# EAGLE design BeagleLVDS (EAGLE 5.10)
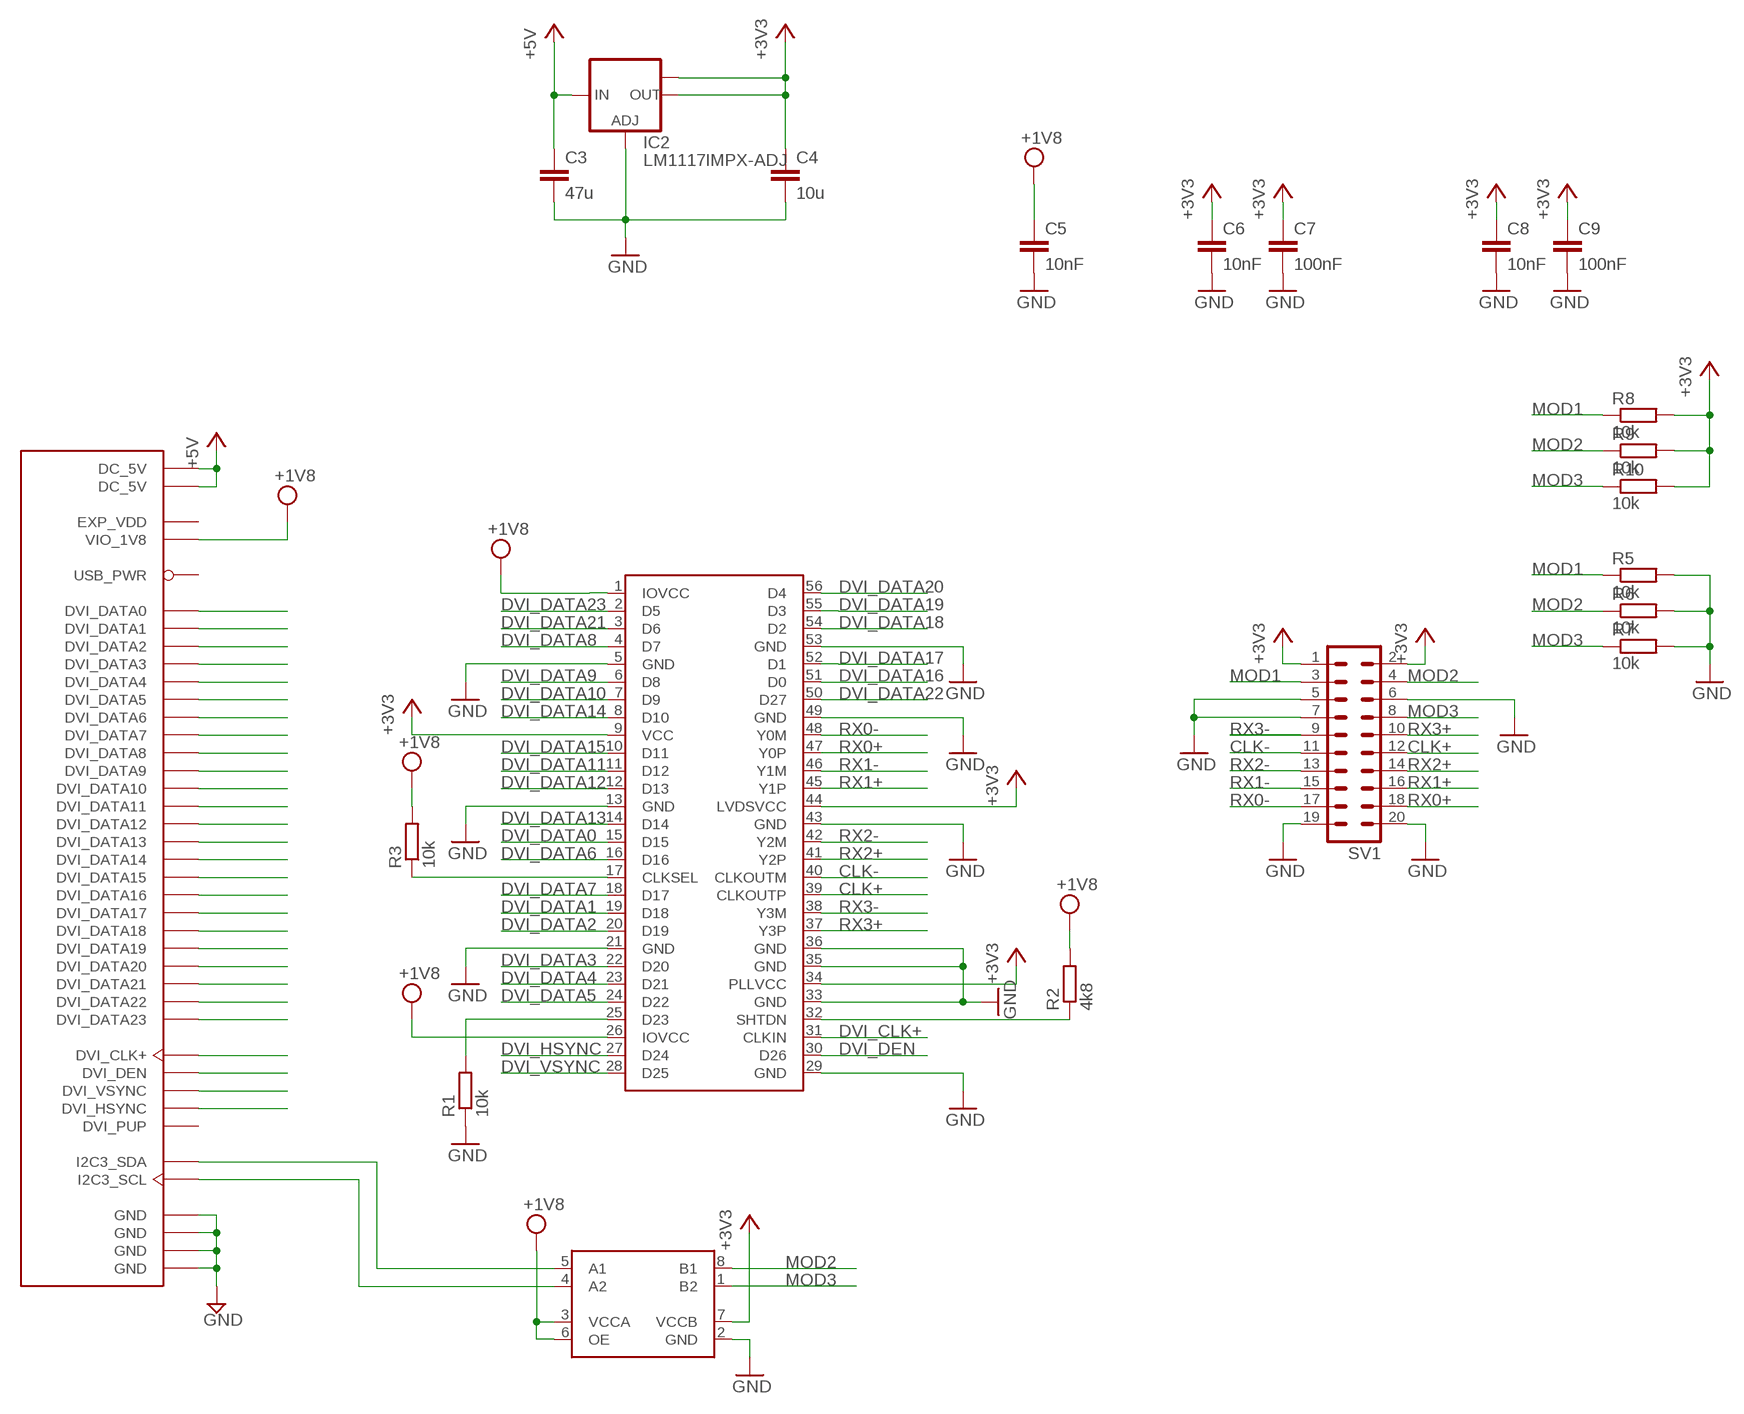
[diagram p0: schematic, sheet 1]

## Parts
C3  47u  C-EUC1206  [C1206]
C4  10u  C-EUC1206  [C1206]
C5  10nF  C-EUC0402  [C0402]
C6  10nF  C-EUC0402  [C0402]
C7  100nF  C-EUC0603  [C0603]
C8  10nF  C-EUC0402  [C0402]
C9  100nF  C-EUC0603  [C0603]
DCU1  TXS0102  [DCU]
IC2  LM1117IMPX-ADJ  [SOT223]
R1  10k  R-EU_R0402  [R0402]
R2  4k8  R-EU_R0402  [R0402]
R3  10k  R-EU_R0402  [R0402]
R5  10k  R-EU_R0402  [R0402]
R6  10k  R-EU_R0402  [R0402]
R7  10k  R-EU_R0402  [R0402]
R8  10k  R-EU_R0402  [R0402]
R9  10k  R-EU_R0402  [R0402]
R10  10k  R-EU_R0402  [R0402]
SV1  MA10-2  [MA10-2]
U$1  LCD_EXPANSION_HEADERSSMALL_PADS  LCD_EXPANSION_HEADERS  [MALE_HEADER_2X10_50MIL]
U$2  SN75LVDS83B  [PSOP56]

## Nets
+1V8: C5.1 DCU1.3(VCCA) DCU1.6(OE) R2.2 R3.2 U$1.P13_2(VIO_1V8) U$2.1(IOVCC) U$2.26(IOVCC)
+3V3: C4.1 C6.1 C7.1 C8.1 C9.1 DCU1.7(VCCB) IC2.2(OUT) IC2.TAB(OUT1) R8.2 R9.2 R10.2 SV1.1 SV1.2 U$2.9(VCC) U$2.34(PLLVCC) U$2.44(LVDSVCC)
+5V: C3.1 IC2.3(IN) U$1.P11_1(DC_5V) U$1.P11_2(DC_5V)
CLK+: SV1.12 U$2.39(CLKOUTP)
CLK-: SV1.11 U$2.40(CLKOUTM)
DVI_CLK+: U$1.P13_16(DVI_CLK+) U$2.31(CLKIN)
DVI_DATA0: U$1.P11_4(DVI_DATA0) U$2.15(D15)
DVI_DATA1: U$1.P11_3(DVI_DATA1) U$2.19(D18)
DVI_DATA2: U$1.P11_6(DVI_DATA2) U$2.20(D19)
DVI_DATA3: U$1.P11_5(DVI_DATA3) U$2.22(D20)
DVI_DATA4: U$1.P11_8(DVI_DATA4) U$2.23(D21)
DVI_DATA5: U$1.P11_7(DVI_DATA5) U$2.24(D22)
DVI_DATA6: U$1.P13_15(DVI_DATA6) U$2.16(D16)
DVI_DATA7: U$1.P13_9(DVI_DATA7) U$2.18(D17)
DVI_DATA8: U$1.P13_11(DVI_DATA8) U$2.4(D7)
DVI_DATA9: U$1.P13_13(DVI_DATA9) U$2.6(D8)
DVI_DATA10: U$1.P11_10(DVI_DATA10) U$2.7(D9)
DVI_DATA11: U$1.P11_16(DVI_DATA11) U$2.11(D12)
DVI_DATA12: U$1.P11_9(DVI_DATA12) U$2.12(D13)
DVI_DATA13: U$1.P13_10(DVI_DATA13) U$2.14(D14)
DVI_DATA14: U$1.P11_12(DVI_DATA14) U$2.8(D10)
DVI_DATA15: U$1.P13_7(DVI_DATA15) U$2.10(D11)
DVI_DATA16: U$1.P13_8(DVI_DATA16) U$2.51(D0)
DVI_DATA17: U$1.P13_5(DVI_DATA17) U$2.52(D1)
DVI_DATA18: U$1.P13_6(DVI_DATA18) U$2.54(D2)
DVI_DATA19: U$1.P11_13(DVI_DATA19) U$2.55(D3)
DVI_DATA20: U$1.P13_3(DVI_DATA20) U$2.56(D4)
DVI_DATA21: U$1.P13_4(DVI_DATA21) U$2.3(D6)
DVI_DATA22: U$1.P11_14(DVI_DATA22) U$2.50(D27)
DVI_DATA23: U$1.P11_11(DVI_DATA23) U$2.2(D5)
DVI_DEN: U$1.P13_17(DVI_DEN) U$2.30(D26)
DVI_HSYNC: U$1.P13_18(DVI_HSYNC) U$2.27(D24)
DVI_VSYNC: U$1.P11_17(DVI_VSYNC) U$2.28(D25)
GND: C3.2 C4.2 C5.2 C6.2 C7.2 C8.2 C9.2 DCU1.2(GND) IC2.1(ADJ) R1.1 R5.2 R6.2 R7.2 SV1.5 SV1.6 SV1.7 SV1.19 SV1.20 U$1.P11_19(GND) U$1.P11_20(GND) U$1.P13_19(GND) U$1.P13_20(GND) U$2.5(GND) U$2.13(GND) U$2.21(GND) U$2.29(GND) U$2.33(GND) U$2.35(GND) U$2.36(GND) U$2.43(GND) U$2.49(GND) U$2.53(GND)
MOD1: R5.1 R8.1 SV1.3
MOD2: DCU1.8(B1) R6.1 R9.1 SV1.4
MOD3: DCU1.1(B2) R7.1 R10.1 SV1.8
N$1: R3.1 U$2.17(CLKSEL)
N$2: R1.2 U$2.25(D23)
N$3: R2.1 U$2.32(SHTDN)
N$5: DCU1.5(A1) U$1.P11_15(I2C3_SDA)
N$6: DCU1.4(A2) U$1.P13_14(I2C3_SCL)
RX0+: SV1.18 U$2.47(Y0P)
RX0-: SV1.17 U$2.48(Y0M)
RX1+: SV1.16 U$2.45(Y1P)
RX1-: SV1.15 U$2.46(Y1M)
RX2+: SV1.14 U$2.41(Y2P)
RX2-: SV1.13 U$2.42(Y2M)
RX3+: SV1.10 U$2.37(Y3P)
RX3-: SV1.9 U$2.38(Y3M)
Unconnected: U$1.P11_18(DVI_PUP) U$1.P13_1(EXP_VDD) U$1.P13_12(USB_PWR)

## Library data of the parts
C3-C9 = rcl:C-EU: CAPACITOR, European symbol
DCU1 = TXS0102:TXS0102
IC2 = lm1117:LM1117IMPX-ADJ
R1-R3 R5-R10 = rcl:R-EU_: RESISTOR, European symbol
SV1 = con-lstb:MA10-2: PIN HEADER
U$1 = Beagleboard-XM:LCD_EXPANSION_HEADERS
U$2 = SN75LVDS83B:SN75LVDS83B

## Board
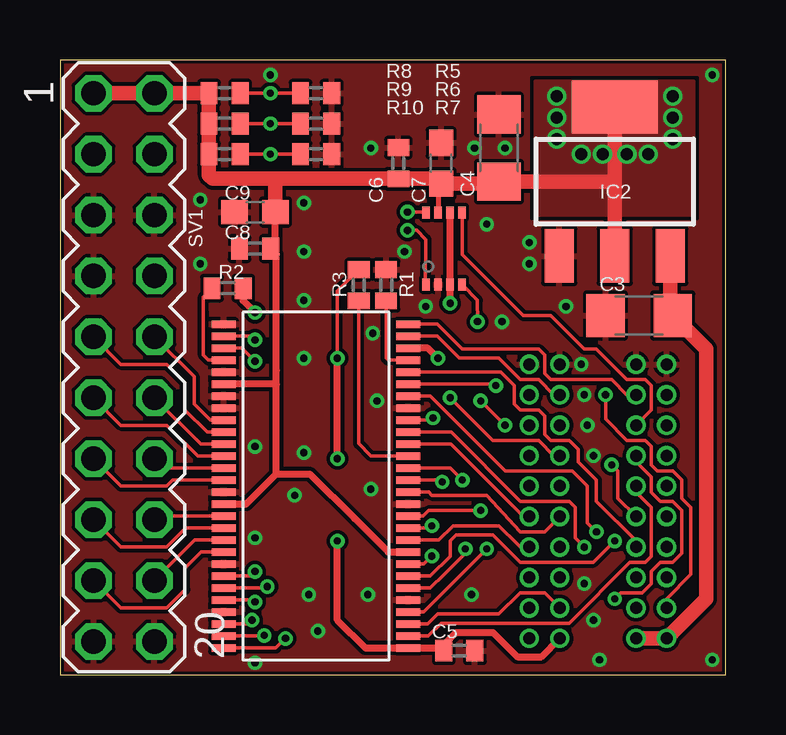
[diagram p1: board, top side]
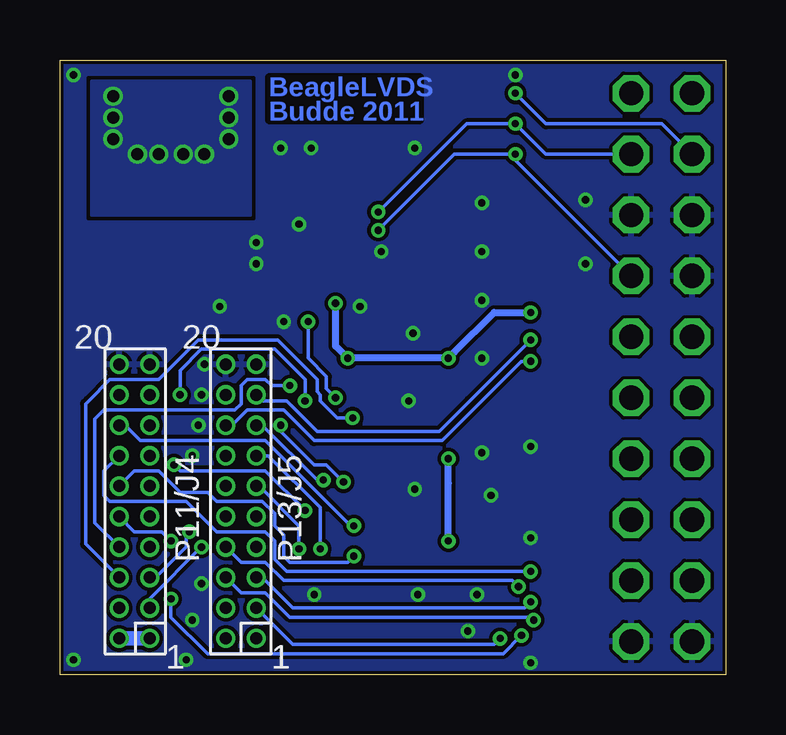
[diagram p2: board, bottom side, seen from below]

Size 27.74 x 25.64 mm. Coordinates in mm from the lower left corner, seen from the top.
Outline: 0,0 27.74,0 27.74,25.64 0,25.64 0,0
Copper layers (1*16): Top 0.035mm / dielectric 1.5mm / Bottom 0.035mm
Design rules "2layer_20110407": minimum track width 0.15mm, minimum drill 0.3mm, track to track 0.15mm, track to pad 0.15mm, pad to pad 0.15mm, via to via 0.15mm, smd to smd 0.15mm, copper to edge 0.15mm, drill to drill 0.2mm, minimum pad ring 0.15mm, minimum via ring 0.15mm, stop-mask expansion 0.15mm, vias tented up to drill 0.3mm, thermal gap 0.15mm

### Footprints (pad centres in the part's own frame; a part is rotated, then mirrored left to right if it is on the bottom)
C1206 = smd 1.6 x 1.8: 1 -1.4,0; 2 1.4,0
C0402 = smd 0.7 x 0.9: 1 -0.65,0; 2 0.65,0
C0603 = smd 1.1 x 1: 1 -0.85,0; 2 0.85,0
DCU = smd 0.3 x 0.5: 1 -0.75,-1.5; 2 -0.25,-1.5; 3 0.25,-1.5; 4 0.75,-1.5; 5 0.75,1.5; 6 0.25,1.5; 7 -0.25,1.5; 8 -0.75,1.5
SOT223 = smd 1.219 x 2.235: 1 -2.311,-3.099; 2 0,-3.099; 3 2.311,-3.099 | smd 3.6 x 2.2: TAB 0,3.099
R0402 = smd 0.7 x 0.9: 1 -0.65,0; 2 0.65,0
MA10-2 = drill 1.016 octagon: 1 -11.43,-1.27; 2 -11.43,1.27; 3 -8.89,-1.27; 4 -8.89,1.27; 5 -6.35,-1.27; 6 -6.35,1.27; 7 -3.81,-1.27; 8 -3.81,1.27; 9 -1.27,-1.27; 10 -1.27,1.27; 11 1.27,-1.27; 12 1.27,1.27; 13 3.81,-1.27; 14 3.81,1.27; 15 6.35,-1.27; 16 6.35,1.27; 17 8.89,-1.27; 18 8.89,1.27; 19 11.43,-1.27; 20 11.43,1.27
MALE_HEADER_2X10_50MIL = drill 0.5 pad 0.8 round: P11_1 -1.778,-5.715; P11_2 -3.048,-5.715; P11_3 -1.778,-4.445; P11_4 -3.048,-4.445; P11_5 -1.778,-3.175; P11_6 -3.048,-3.175; P11_7 -1.778,-1.905; P11_8 -3.048,-1.905; P11_9 -1.778,-0.635; P11_10 -3.048,-0.635; P11_11 -1.778,0.635; P11_12 -3.048,0.635; P11_13 -1.778,1.905; P11_14 -3.048,1.905; P11_15 -1.778,3.175; P11_16 -3.048,3.175; P11_17 -1.778,4.445; P11_18 -3.048,4.445; P11_19 -1.778,5.715; P11_20 -3.048,5.715; P13_1 2.667,-5.715; P13_2 1.397,-5.715; P13_3 2.667,-4.445; P13_4 1.397,-4.445; P13_5 2.667,-3.175; P13_6 1.397,-3.175; P13_7 2.667,-1.905; P13_8 1.397,-1.905; P13_9 2.667,-0.635; P13_10 1.397,-0.635; P13_11 2.667,0.635; P13_12 1.397,0.635; P13_13 2.667,1.905; P13_14 1.397,1.905; P13_15 2.667,3.175; P13_16 1.397,3.175; P13_17 2.667,4.445; P13_18 1.397,4.445; P13_19 2.667,5.715; P13_20 1.397,5.715
PSOP56 = smd 0.3 x 1: 1 -6.75,-3.85; 2 -6.25,-3.85; 3 -5.75,-3.85; 4 -5.25,-3.85; 5 -4.75,-3.85; 6 -4.25,-3.85; 7 -3.75,-3.85; 8 -3.25,-3.85; 9 -2.75,-3.85; 10 -2.25,-3.85; 11 -1.75,-3.85; 12 -1.25,-3.85; 13 -0.75,-3.85; 14 -0.25,-3.85; 15 0.25,-3.85; 16 0.75,-3.85; 17 1.25,-3.85; 18 1.75,-3.85; 19 2.25,-3.85; 20 2.75,-3.85; 21 3.25,-3.85; 22 3.75,-3.85; 23 4.25,-3.85; 24 4.75,-3.85; 25 5.25,-3.85; 26 5.75,-3.85; 27 6.25,-3.85; 28 6.75,-3.85; 29 6.75,3.85; 30 6.25,3.85; 31 5.75,3.85; 32 5.25,3.85; 33 4.75,3.85; 34 4.25,3.85; 35 3.75,3.85; 36 3.25,3.85; 37 2.75,3.85; 38 2.25,3.85; 39 1.75,3.85; 40 1.25,3.85; 41 0.75,3.85; 42 0.25,3.85; 43 -0.25,3.85; 44 -0.75,3.85; 45 -1.25,3.85; 46 -1.75,3.85; 47 -2.25,3.85; 48 -2.75,3.85; 49 -3.25,3.85; 50 -3.75,3.85; 51 -4.25,3.85; 52 -4.75,3.85; 53 -5.25,3.85; 54 -5.75,3.85; 55 -6.25,3.85; 56 -6.75,3.85

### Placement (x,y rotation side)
C3  24.13,14.99 180 top
C4  18.29,21.97 90 top
C5  16.64,1.02 0 top
C6  14.1,21.34 90 top
C7  15.88,21.34 90 top
C8  8.13,17.78 180 top
C9  8.13,19.3 180 top
DCU1  16,17.78 0 top
IC2  23.11,20.57 0 top
R1  13.59,16.26 270 top
R2  6.99,16.13 0 top
R3  12.45,16.26 90 top
R5  10.67,24.26 0 top
R6  10.67,22.99 0 top
R7  10.67,21.72 0 top
R8  6.86,24.26 180 top
R9  6.86,22.99 180 top
R10  6.86,21.72 180 top
SV1  2.67,12.83 270 top
U$1  22.23,7.24 0 bottom
U$2  10.67,7.87 90 top

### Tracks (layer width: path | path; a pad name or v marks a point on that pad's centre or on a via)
+1V8  (via drill 0.3 pad 0.6)
  Top 0.15: R3.2 11.56,16.02 v11.56,13.21
  Top 0.3: U$1.P13_2 20.07,0.76 19.05,0.76 18.8,1.02 18.03,1.78 16.51,1.78 16,1.28 C5.1 15.88,1.12 U$2.1 12.72,1.12 11.56,2.29 v11.56,5.59 | U$2.26 15.33,13.62 v15.75,13.21 | R2.2 7.63,15.61 v8.13,15.11 | v16.26,15.49 16.26,15.89 DCU1.3 DCU1.6 | v11.56,9.02 v11.56,13.21
  Bottom 0.3: v11.56,5.59 11.56,8 v11.56,9.02 | v8.13,15.11 9.65,15.11 11.3,13.46 v11.56,13.21 v15.75,13.21 16.26,13.72 v16.26,15.49
+3V3  (via drill 0.5 pad 0.6)
  Top 0.2: DCU1.7 15.75,20.57 C4.1
  Top 0.3: 9.02,12.12 8.95,12.12 U$2.34 9.02,12.12 | U$2.9 13.67,5.12 12.28,6.52 10.41,8.38 9.02,8.38 | R10.2 6.22,21.7 | C9.1 8.98,17.98 C8.1 9.02,17.54 9.02,12.7 9.02,12.12 | 9.02,8.38 9.02,12.12 | U$2.44 7.76,7.12 9.02,8.38
  Top 0.61: SV1.1 SV1.2 R8.2 R9.2 R10.2 | 23.11,20.57 IC2.TAB 23.11,20.57 | 23.11,20.57 IC2.2 | 23.11,20.57 C4.1 18.67,20.49 C7.1 15.88,20.69 C6.1 6.37,20.69 | 6.37,20.69 6.22,20.83 6.21,20.84 | 6.21,20.84 R10.2 | 6.21,20.84 R10.2 | 6.37,20.69 8.98,20.69 C9.1
  other vias: 20.7,24.13 20.7,23.24 22.61,21.72 24.51,21.72 25.53,24.13 25.53,23.24 25.53,22.35 21.72,21.72 23.62,21.72 20.7,22.35
  pour Top (isolate 0.254, no thermals): 19.81,24.77 19.81,19.18 26.42,19.18 26.42,24.77
  pour Bottom (isolate 0.254, no thermals): 19.81,24.77 19.81,19.18 26.42,19.18 26.42,24.77
+5V
  Top 0.61: IC2.3 25.43,15.01 C3.1 26.92,13.59 26.92,13.08 26.92,3.17 U$1.P11_2 U$1.P11_1
  Bottom 0.61: U$1.P11_2 U$1.P11_1
CLK+
  Top 0.15: U$2.39 5.87,9.62 SV1.12
CLK-
  Top 0.15: U$2.40 5.74,9.12 4.45,10.41 2.54,10.41 SV1.11
DVI_CLK+  (via drill 0.3 pad 0.6)
  Top 0.15: v8.13,13.08 7.75,13.46 7.58,13.62 U$2.31
  Bottom 0.15: U$1.P13_16 20.57,10.41 19.94,11.05 18.41,11.05 17.14,9.78 11.81,9.78 8.51,13.08 v8.13,13.08
DVI_DATA0  (via drill 0.3 pad 0.6)
  Top 0.15: U$1.P11_4 25.27,3.17 26.29,4.19 26.29,6.99 25.91,7.37 25.91,8.13 25.53,8.51 25.02,8.51 24.89,8.51 24.64,8.76 24.64,9.53 24.38,9.78 23.62,9.78 22.73,10.67 v22.73,11.68 | U$2.15 15.85,8.13 v15.93,8.05 | v18.54,10.41 v17.53,11.43
  Bottom 0.15: v17.53,11.43 17.53,12.32 18.8,13.59 19.3,13.59 21.84,13.59 22.73,12.7 v22.73,11.68 | v15.93,8.05 16.64,8.76 17.14,8.76 18.54,10.16 v18.54,10.41
DVI_DATA1  (via drill 0.3 pad 0.6)
  Top 0.15: U$2.19 16.29,10.12 19.18,7.24 21.21,7.24 21.46,6.99 21.46,5.71 v21.84,5.33
  Bottom 0.15: v21.84,5.33 24,3.17 U$1.P11_3
DVI_DATA2  (via drill 0.3 pad 0.6)
  Top 0.15: U$2.20 15.45,10.62 v15.54,10.72
  Bottom 0.15: U$1.P11_6 26.67,5.46 26.67,11.3 26.54,11.43 25.65,12.32 23.62,12.32 21.97,13.97 18.67,13.97 17.02,12.32 17.02,11.81 16.89,11.68 16.89,11.43 16.18,10.72 v15.54,10.72
DVI_DATA3  (via drill 0.3 pad 0.6)
  Top 0.15: v22.35,5.97 21.97,6.35 21.97,7.11 21.97,7.87 21.34,8.51 18.54,8.51 16.13,10.92 15.43,11.62 U$2.22
  Bottom 0.15: v22.35,5.97 22.48,5.84 22.48,5.46 22.48,5.33 23.75,4.06 U$1.P11_5
DVI_DATA4  (via drill 0.3 pad 0.6)
  Top 0.15: U$2.23 17.98,12.12 v18.16,12.06
  Bottom 0.15: v18.16,12.06 18.92,12.06 | 18.92,12.06 19.18,12.32 | 18.92,12.06 19.18,12.32 | 19.18,12.32 19.94,12.32 20.19,12.06 20.19,11.3 20.45,11.05 25.91,11.05 26.29,10.67 26.29,6.35 U$1.P11_8
DVI_DATA5
  Top 0.15: U$2.24 18.36,12.62 18.92,12.06 18.92,11.3 19.18,11.05 19.94,11.05 20.19,10.79 20.19,10.03 20.45,9.78 21.21,9.78 21.59,9.4 21.59,8.89 22.35,8.13 22.35,7.24 24,5.59 U$1.P11_7
DVI_DATA6  (via drill 0.3 pad 0.6)
  Top 0.15: v16.76,8.13 16.26,8.64 14.53,8.64 U$2.16
  Bottom 0.15: U$1.P13_15 19.3,10.41 17.02,8.13 v16.76,8.13
DVI_DATA7
  Top 0.15: U$1.P13_9 19.3,6.6 16.28,9.62 U$2.18
DVI_DATA8  (via drill 0.3 pad 0.6)
  Top 0.15: v17.78,5.26 15.15,2.62 U$2.4
  Bottom 0.15: v17.78,5.26 17.78,6.22 19.43,7.87 U$1.P13_11
DVI_DATA9  (via drill 0.3 pad 0.6)
  Top 0.15: v16.89,5.26 16.89,5.08 16,4.19 15.44,3.62 U$2.6
  Bottom 0.15: U$1.P13_13 19.05,9.14 16.89,6.99 v16.89,5.26
DVI_DATA10  (via drill 0.3 pad 0.6)
  Top 0.15: U$2.7 15.43,4.12 16.26,4.95 16.26,5.59 16.51,5.84 18.03,5.84 19.18,4.7 22.23,4.7 v23.11,5.59
  Bottom 0.15: v23.11,5.59 23.5,5.97 23.62,5.97 24.64,5.97 U$1.P11_10
DVI_DATA11  (via drill 0.3 pad 0.6)
  Top 0.15: U$2.11 15.39,6.12 v15.49,6.22
  Bottom 0.15: v15.49,6.22 15.62,6.22 19.18,9.78 24.38,9.78 25.02,10.41 U$1.P11_16
DVI_DATA12  (via drill 0.3 pad 0.6)
  Top 0.15: U$2.12 15.13,6.62 15.37,6.86 v17.53,6.86 | v22.99,8.76 23.24,8.51 23.24,7.37 U$1.P11_9
  Bottom 0.15: v17.53,6.86 19.18,8.51 22.73,8.51 v22.99,8.76
DVI_DATA13
  Top 0.15: U$1.P13_10 20.19,5.97 19.18,5.97 17.78,7.49 15.49,7.49 15.36,7.62 U$2.14
DVI_DATA14  (via drill 0.3 pad 0.6)
  Top 0.15: U$2.8 15.16,4.62 v15.49,4.95
  Bottom 0.15: v15.49,4.95 15.75,4.7 18.16,4.7 18.41,4.95 18.41,5.84 18.8,6.22 18.8,6.73 19.3,7.24 21.21,7.24 21.59,7.62 22.73,7.62 23.62,8.51 24.64,8.51 U$1.P11_12
DVI_DATA15
  Top 0.15: U$2.10 15.78,5.62 16.38,6.22 18.29,6.22 19.05,5.46 19.18,5.33 U$1.P13_7
DVI_DATA16  (via drill 0.3 pad 0.6)
  Top 0.15: U$2.51 8.58,3.62 v8.64,3.68
  Bottom 0.15: U$1.P13_8 20.19,4.7 19.18,4.7 18.41,3.94 8.89,3.94 v8.64,3.68
DVI_DATA17  (via drill 0.3 pad 0.6)
  Top 0.15: U$2.52 8.08,3.12 v8.13,3.05
  Bottom 0.15: v8.13,3.05 8.38,2.79 9.02,2.79 18.03,2.79 19.3,4.06 U$1.P13_5
DVI_DATA18  (via drill 0.3 pad 0.6)
  Top 0.15: U$2.54 7.84,2.12 v8,2.29
  Bottom 0.15: v8,2.29 8.13,2.41 18.16,2.41 19.18,3.43 20.19,3.43 U$1.P13_6
DVI_DATA19  (via drill 0.3 pad 0.6)
  Top 0.15: v23.11,3.17 23.37,3.43 24.13,3.43 24.26,3.43 24.64,3.81 24.64,4.32 25.02,4.7 25.53,4.7 25.91,5.08 25.91,6.86 25.53,7.24 25.02,7.24 24.64,7.62 24.64,8.13 24.64,8.26 24,8.89 U$1.P11_13 | U$2.55 8.48,1.62 v8.51,1.65
  Bottom 0.15: v8.51,1.65 9.27,0.89 21.08,0.89 21.59,0.89 23.11,2.41 v23.11,3.17
DVI_DATA20  (via drill 0.3 pad 0.6)
  Top 0.15: U$2.56 9,1.12 v9.4,1.52
  Bottom 0.15: v9.4,1.52 9.65,1.27 18.03,1.27 U$1.P13_3
DVI_DATA21
  Top 0.15: U$2.3 15.33,2.12 15.75,2.54 18.29,2.54 19.18,3.43 20.19,3.43 U$1.P13_4
DVI_DATA22  (via drill 0.3 pad 0.6)
  Top 0.15: U$2.50 7.93,4.12 v8.13,4.32
  Bottom 0.15: U$1.P11_14 25.91,8.51 25.91,7.49 25.65,7.24 22.48,7.24 21.21,5.97 19.18,5.97 18.8,5.59 18.8,4.83 18.29,4.32 v8.13,4.32
DVI_DATA23
  Top 0.15: U$2.2 15.34,1.62 15.88,2.16 21.21,2.16 23.75,4.7 24.38,4.7 24.64,4.95 24.64,6.99 24,7.62 U$1.P11_11
DVI_DEN  (via drill 0.3 pad 0.6)
  Top 0.15: v8.13,13.97 7.97,14.12 U$2.30
  Bottom 0.15: U$1.P13_17 19.3,11.43 18.29,11.43 17.02,10.16 11.94,10.16 10.67,11.43 v8.13,13.97
DVI_HSYNC
  Top 0.15: U$2.27 15.72,14.12 16.64,13.21 18.29,13.21 19.18,12.32 19.94,12.32 20.57,11.68 U$1.P13_18
DVI_VSYNC
  Top 0.15: U$2.28 15.73,14.62 16.76,13.59 19.94,13.59 20.19,13.34 20.19,12.57 20.45,12.32 22.99,12.32 23.62,11.68 U$1.P11_17
GND  (via drill 0.3 pad 0.6)
  other vias: 10.36,3.35 22.23,2.29 21.84,3.81 21.84,11.68 12.83,3.35 21.72,12.95 21.97,10.41 22.23,9.14 18.41,14.73 21.08,15.37 27.18,0.64 22.48,0.64 8.13,0.51 10.74,1.83 17.14,3.35 27.18,25.02 18.54,21.97 12.95,21.97 14.35,17.65 5.84,19.81 5.84,17.14 17.78,18.8 17.27,21.97 15.24,15.37 13.21,11.43 13.03,14.25 8.13,9.53 10.16,9.27 12.95,7.75 9.78,7.49 8.13,5.71 10.16,13.21 10.16,15.62 8.76,25.02 19.56,18.03 19.56,17.14 10.16,19.68 10.16,17.65
  pour Top (rank 6): -0.38,25.91 28.07,25.91 27.69,-0.13 -0.38,-0.13
  pour Bottom (rank 6): -0.76,26.29 27.81,26.04 27.94,-0.64 -0.76,-0.25
MOD1  (via drill 0.3 pad 0.6)
  Top 0.15: R8.1 v8.76,24.26 R5.1
  Bottom 0.15: SV1.3 2.67,22.99 7.49,22.99 v8.76,24.26
MOD2  (via drill 0.3 pad 0.6)
  Top 0.15: R9.1 v8.76,22.99 R6.1 | DCU1.8 15.23,19.3 v14.48,19.3
  Bottom 0.15: SV1.4 7.49,21.72 v8.76,22.99 10.79,22.99 v14.48,19.3
MOD3  (via drill 0.3 pad 0.6)
  Top 0.15: R7.1 v8.76,21.72 R10.1 | DCU1.1 15.23,16.26 15.24,18.16 14.86,18.54 v14.48,18.54
  Bottom 0.15: SV1.8 8.76,21.46 v8.76,21.72 11.3,21.72 v14.48,18.54
N$1
  Top 0.15: R3.1 12.45,9.65 12.95,9.14 12.97,9.12 U$2.17
N$2
  Top 0.15: R1.2 13.59,13.21 13.67,13.12 U$2.25
N$3
  Top 0.15: R2.1 5.97,15.76 5.97,15.11 5.97,13.34 6.18,13.12 U$2.32
N$5
  Top 0.15: U$1.P11_15 24.64,11.05 24.64,12.06 24.38,12.32 23.62,12.32 22.35,13.59 21.84,13.59 20.45,14.99 19.3,14.99 16.75,17.54 DCU1.5
N$6  (via drill 0.3 pad 0.6)
  Top 0.15: U$1.P13_14 20.57,9.14 19.94,9.78 18.03,9.78 16.38,11.43 v16.26,11.56 | v17.4,14.73 17.39,15.63 DCU1.4
  Bottom 0.15: v16.26,11.56 16.64,11.94 16.64,12.45 17.4,13.21 v17.4,14.73
RX0+
  Top 0.15: U$2.47 6.51,5.62 5.62,5.62 SV1.18
RX0-
  Top 0.15: 6.78,5.12 U$2.48 5.89,5.12 5.21,4.45 5.21,3.56 4.45,2.79 2.54,2.79 SV1.17
RX1+
  Top 0.15: U$2.45 4.08,6.62 SV1.16
RX1-
  Top 0.15: U$2.46 5.24,6.12 4.45,5.33 2.54,5.33 SV1.15
RX2+
  Top 0.15: U$2.41 4.33,8.62 SV1.14
RX2-
  Top 0.15: U$2.42 4.7,8.12 4.45,7.87 2.54,7.87 SV1.13
RX3+
  Top 0.15: SV1.10 5.59,12.45 5.59,11.3 6.27,10.62 U$2.37
RX3-
  Top 0.15: SV1.9 2.54,12.95 4.45,12.95 5.21,12.19 5.21,11.05 6.13,10.12 U$2.38

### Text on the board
Bottom: BeagleLVDS | Budde 2011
